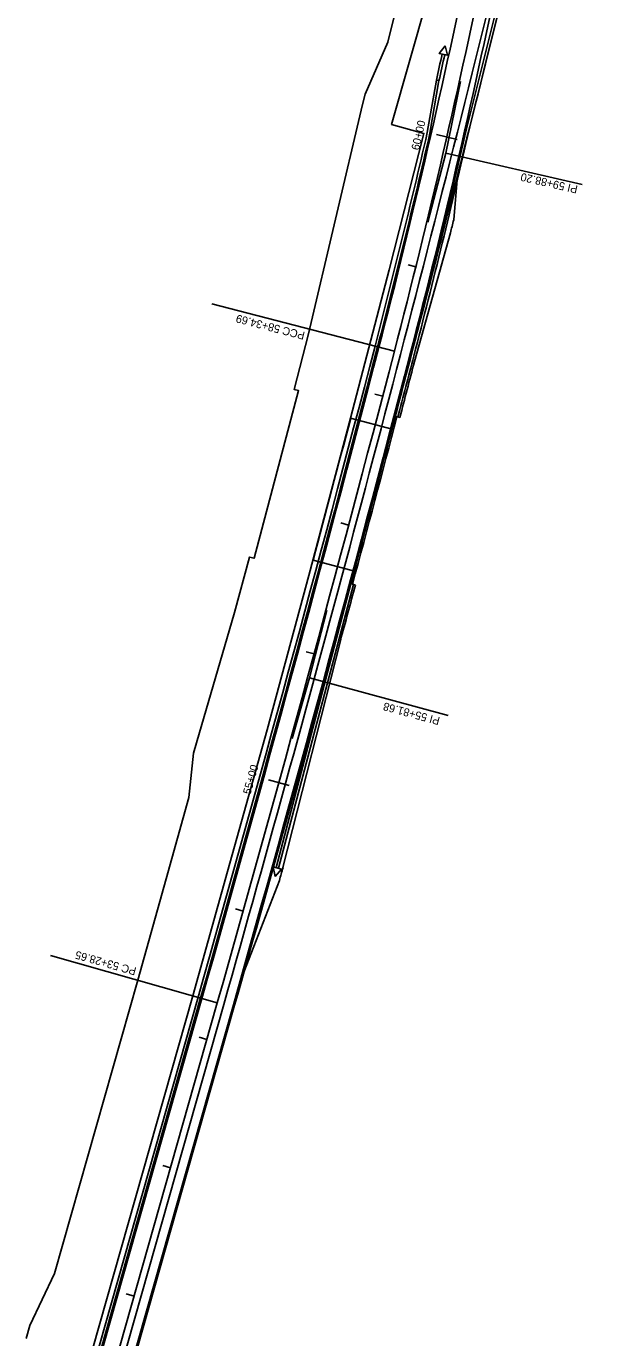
# Model space of a CAD drawing. Extents: x 1445610 to 1446352, y 2042797 to 2056486.
# Drawn here: x 1445890 to 1446316, y 2054904 to 2055888 of the extents above; entities that cross this region are included whole.
import ezdxf

# ---------------------------------------------------------------- set-up
doc = ezdxf.new("R2010")
doc.units = 0
for name, color, linetype in [('20', 7, 'Continuous'), ('Default', 7, 'Continuous'), ('MOT_Barrier Wall', 7, 'Continuous'), ('MOT_TIAB', 7, 'Continuous'), ('R_Bridge', 7, 'Continuous'), ('R_Horz Alg', 7, 'Continuous'), ('R_Horz Alg Annot', 7, 'Continuous'), ('R_Horz Alg Annot_Detour', 7, 'Continuous'), ('R_Horz Alg Stationing_Detour', 7, 'Continuous'), ('R_Proposed Road', 7, 'Continuous'), ('R_Shld', 7, 'Continuous')]:
    doc.layers.add(name, color=color, linetype=linetype)

msp = doc.modelspace()

# ---------------------------------------------------------------- linework, layer by layer
at = {"layer": '20'}
for points in [[(1445890, 2054904.01), (1445892.73, 2054913.63), (1445911.13, 2054952.61), (1445973.51, 2055172.55), (1445994.9, 2055248.48), (1446011.88, 2055309.49), (1446015.35, 2055342.71), (1446017.47, 2055350.41), (1446046.17, 2055448.11), (1446057.37, 2055489.69), (1446060.75, 2055488.79), (1446094.07, 2055614.46), (1446090.68, 2055615.35), (1446101.56, 2055657.03), (1446141.98, 2055829.05), (1446143.93, 2055836.79), (1446160.91, 2055875.76), (1446223.23, 2056125.73)], [(1446204, 2055955.28), (1446163.78, 2055814.06), (1446188.04, 2055807.22), (1446161.93, 2055705.11), (1446133.09, 2055593.77), (1446101.82, 2055475.94), (1446070.44, 2055360.18), (1446040.84, 2055253.88), (1446014.88, 2055160.82), (1445891.32, 2054725.14)]]:
    msp.add_lwpolyline(points, dxfattribs=at)
at = {"layer": 'Default'}
msp.add_arc((1423960.81, 2061415.35), 22923.81, 345.013473, 345.288407, dxfattribs=at)
at = {"layer": 'MOT_Barrier Wall'}
for p, q in [((1446219.86, 2055810.7), (1446254.08, 2055947.71)), ((1446221.81, 2055810.26), (1446256.02, 2055947.23)), ((1446201.61, 2055866.71), (1446203.56, 2055866.28)), ((1446190.48, 2055807.83), (1446197.32, 2055847.23)), ((1446192.44, 2055807.44), (1446199.27, 2055846.8)), ((1446197.32, 2055847.23), (1446199.27, 2055846.8)), ((1446166.56, 2055595.23), (1446168.49, 2055594.72)), ((1446077.16, 2055256.89), (1446133.24, 2055469.59)), ((1446079.1, 2055256.38), (1446135.17, 2055469.07)), ((1446133.24, 2055469.58), (1446135.17, 2055469.07)), ((1446079.1, 2055256.38), (1446077.16, 2055256.89)), ((1445895.17, 2054724.05), (1446018.72, 2055159.73)), ((1445897.09, 2054723.5), (1446020.65, 2055159.18))]:
    msp.add_line(p, q, dxfattribs=at)
for centre, radius, start, end in [((1440620.51, 2057085.26), 5712.58, 347.48355, 347.68355), ((1440620.51, 2057085.26), 5714.58, 347.48355, 347.68355), ((1440620.51, 2057085.26), 5742.58, 345.430397, 347.17648), ((1440620.51, 2057085.26), 5744.58, 345.430397, 347.17648), ((1440620.51, 2057085.26), 5714.58, 345.4304, 347.08301), ((1440620.51, 2057085.26), 5716.58, 345.4304, 347.08355), ((1423960.81, 2061415.35), 22927.81, 344.166667, 345.430397), ((1423960.81, 2061415.35), 22929.81, 344.166667, 345.430397), ((1423960.81, 2061415.35), 22955.81, 345.313167, 345.430397), ((1423960.81, 2061415.35), 22957.81, 345.313152, 345.430397)]:
    msp.add_arc(centre, radius, start, end, dxfattribs=at)
at = {"layer": 'MOT_TIAB'}
for points in [[(1446204.01, 2055873.02), (1446205.65, 2055865.82), (1446199.52, 2055867.16)], [(1446076.43, 2055250.18), (1446075.1, 2055257.43), (1446081.16, 2055255.83)]]:
    msp.add_lwpolyline(points, close=True, dxfattribs=at)
at = {"layer": 'R_Bridge'}
for p, q in [((1446166.56, 2055595.24), (1446167.77, 2055594.92)), ((1446133.09, 2055593.77), (1446165.23, 2055585.25)), ((1446104.9, 2055487.44), (1446137.04, 2055478.92)), ((1446133.24, 2055469.58), (1446134.45, 2055469.26))]:
    msp.add_line(p, q, dxfattribs=at)
for radius, start, end in [(22955.81, 344.988714, 345.313167), (22957.06, 344.988723, 345.313158)]:
    msp.add_arc((1423960.81, 2061415.35), radius, start, end, dxfattribs=at)
at = {"layer": 'R_Horz Alg'}
msp.add_line((1445909.6, 2054719.96), (1446033.15, 2055155.64), dxfattribs=at)
for centre, radius, start, end in [((1440620.51, 2057085.26), 5729.58, 345.4304, 348.5), ((1423960.81, 2061415.35), 22942.81, 344.166667, 345.430397)]:
    msp.add_arc(centre, radius, start, end, dxfattribs=at)
at = {"layer": 'R_Horz Alg Annot'}
for p, q in [((1446204.46, 2055792.53), (1446215.35, 2055846.09)), ((1446204.46, 2055792.53), (1446190.99, 2055740.71)), ((1446306.45, 2055768.92), (1446204.46, 2055792.53)), ((1446102.19, 2055399.06), (1446115.34, 2055449.67)), ((1446102.19, 2055399.06), (1446089.33, 2055353.73)), ((1446206.1, 2055370.83), (1446102.19, 2055399.06))]:
    msp.add_line(p, q, dxfattribs=at)
at = {"layer": 'R_Horz Alg Annot_Detour'}
for points in [[(1446165.84, 2055643.95), (1446029.06, 2055679.5)], [(1446033.15, 2055155.64), (1445908.09, 2055191.11)]]:
    msp.add_lwpolyline(points, dxfattribs=at)
at = {"layer": 'R_Horz Alg Stationing_Detour'}
for points in [[(1446197.32, 2055806.32), (1446212.91, 2055802.74)], [(1446176.09, 2055708.7), (1446181.91, 2055707.26)], [(1446151.29, 2055611.91), (1446157.09, 2055610.39)], [(1446125.78, 2055515.24), (1446131.58, 2055513.7)], [(1446099.85, 2055418.69), (1446105.64, 2055417.12)], [(1446071.58, 2055322.78), (1446087, 2055318.53)], [(1446046.74, 2055225.93), (1446052.51, 2055224.31)], [(1446019.56, 2055129.71), (1446025.34, 2055128.07)], [(1445992.28, 2055033.5), (1445998.05, 2055031.87)], [(1445965, 2054937.3), (1445970.77, 2054935.66)]]:
    msp.add_lwpolyline(points, dxfattribs=at)
at = {"layer": 'R_Proposed Road'}
for p, q in [((1446226.97, 2055863.77), (1446308.23, 2056189.67)), ((1446234.73, 2055861.84), (1446315.99, 2056187.74)), ((1445898.05, 2054723.23), (1446021.61, 2055158.91)), ((1445914.41, 2054718.59), (1446037.96, 2055154.27)), ((1445921.14, 2054716.68), (1446044.7, 2055152.36)), ((1445922.1, 2054716.41), (1446045.66, 2055152.09))]:
    msp.add_line(p, q, dxfattribs=at)
for centre, radius, start, end in [((1440620.51, 2057085.26), 5717.58, 345.4304, 348.5), ((1440620.51, 2057085.26), 5741.58, 345.430397, 348.5), ((1423960.81, 2061415.35), 22947.81, 344.166667, 346), ((1423960.81, 2061415.35), 22955.81, 345.318167, 346), ((1423960.81, 2061415.35), 22930.81, 344.166667, 345.430397), ((1423960.81, 2061415.35), 22954.81, 344.166667, 345.430397), ((1423960.81, 2061415.35), 22955.81, 344.166667, 344.988714)]:
    msp.add_arc(centre, radius, start, end, dxfattribs=at)
at = {"layer": 'R_Shld'}
for p, q in [((1446210.29, 2055742.39), (1446213.1, 2055775.79)), ((1446180.87, 2055636.17), (1446207.81, 2055732.69)), ((1446169.94, 2055594.34), (1446167.77, 2055594.92)), ((1446136.63, 2055468.69), (1446134.46, 2055469.26)), ((1446125.39, 2055426.94), (1446082.39, 2055256.93)), ((1446053.48, 2055179.72), (1446079.7, 2055247.28))]:
    msp.add_line(p, q, dxfattribs=at)
for centre, radius, start, end in [((1423960.81, 2061415.35), 22961.31, 345.67104, 345.69604), ((1424944.63, 2061158.48), 21942.5, 345.310641, 345.42354), ((1424942.67, 2061151.07), 21942.5, 344.87834, 344.991239), ((1423960.81, 2061415.35), 22962.81, 344.41834, 344.44334)]:
    msp.add_arc(centre, radius, start, end, dxfattribs=at)

# ---------------------------------------------------------------- texts
at = {"layer": 'R_Horz Alg Annot_Detour'}
for s, rotation, p in [('PI 59+88.20', 167.1077, (1446303.67, 2055767.99)), ('PCC 58+34.69', 165.4304, (1446099.25, 2055658.31)), ('PI 55+81.68', 164.76498, (1446200.42, 2055369.43)), ('PC 53+28.65', 164.16667, (1445972.98, 2055181.8))]:
    msp.add_text(s, height=6, rotation=rotation, dxfattribs=at).set_placement(p)
at = {"layer": 'R_Horz Alg Stationing_Detour'}
for s, rotation, p in [('60+00', 77.08355, (1446184.29, 2055794.28)), ('55+00', 74.59458, (1446058.05, 2055311.32))]:
    msp.add_text(s, height=6, rotation=rotation, dxfattribs=at).set_placement(p)

doc.saveas('drawing.dxf')
